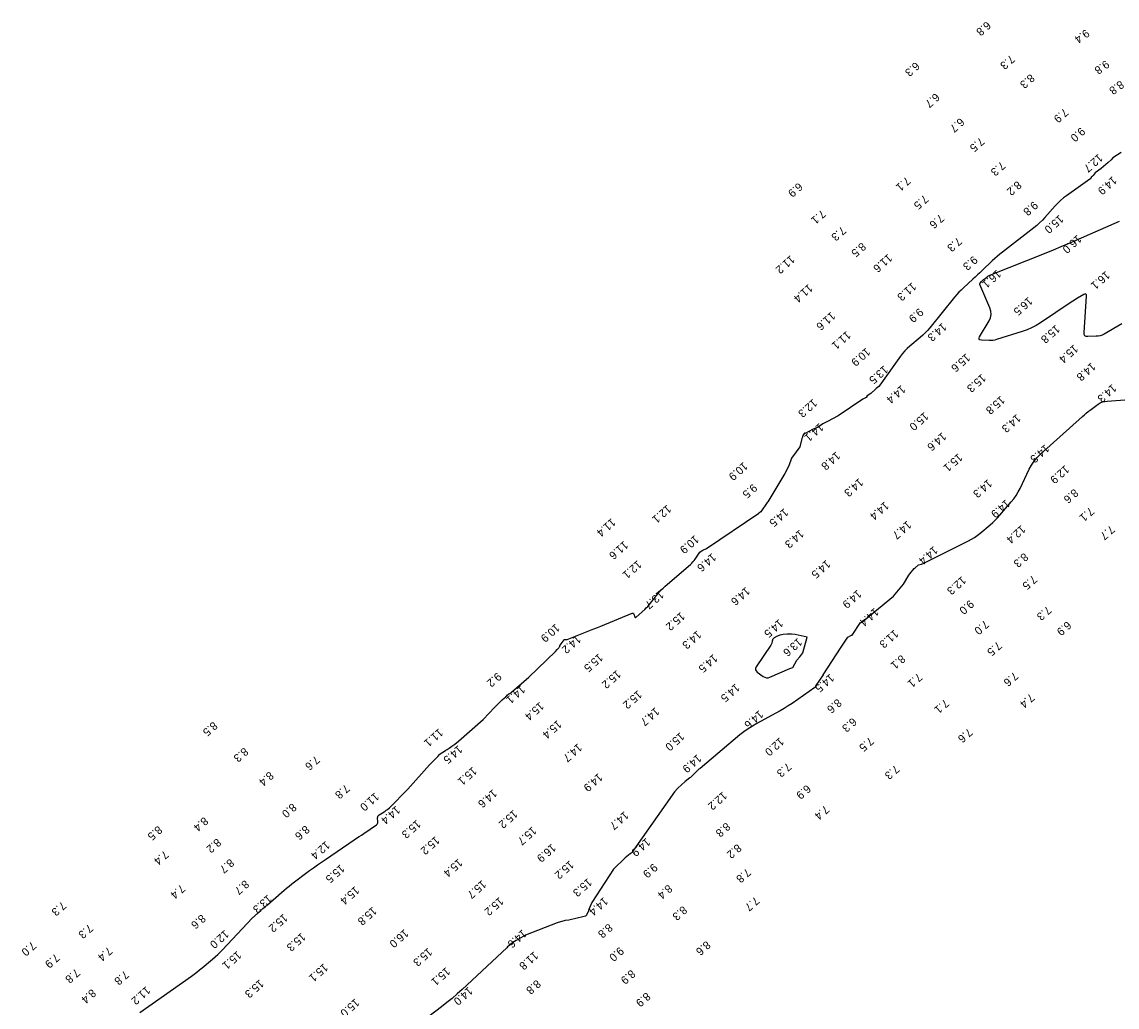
# Model space of a CAD drawing. Extents: x 824616 to 827440, y 158441 to 163197.
# Drawn here: x 825109 to 825793, y 158867 to 159482 of the extents above; entities that cross this region are included whole.
import ezdxf

# ---------------------------------------------------------------- set-up
doc = ezdxf.new("R2010")
doc.units = 0
for name, color, linetype in [('V-CHAN-CONT-EL14', 7, 'Continuous'), ('V-CHAN-CONT-EL16', 7, 'Continuous'), ('V-TOPO-SOUN', 7, 'Continuous')]:
    doc.layers.add(name, color=color, linetype=linetype)

msp = doc.modelspace()

# ---------------------------------------------------------------- linework, layer by layer
at = {"layer": 'V-CHAN-CONT-EL14'}
for points in [[(825795.5, 159400.82), (825790.27, 159397.45), (825789.29, 159396.19), (825787.45, 159394.52), (825783.02, 159390.89), (825779.27, 159388.1), (825778.07, 159386.49), (825777.36, 159385.92), (825776.81, 159385.32), (825776.65, 159385.17), (825776.33, 159384.51), (825776.22, 159384.32), (825776.17, 159384.25), (825776.11, 159384.18), (825776, 159384.1), (825761.4, 159373.83), (825759.48, 159372.4), (825757.65, 159370.87), (825755.91, 159369.23), (825754.27, 159367.49), (825747.88, 159360.31), (825746.24, 159358.56), (825744.53, 159356.89), (825742.75, 159355.29), (825740.89, 159353.78), (825721.38, 159338.58), (825719.73, 159337.26), (825718.1, 159335.9), (825716.52, 159334.5), (825714.96, 159333.06), (825708.62, 159327.04), (825707.18, 159325.68), (825705.72, 159324.32), (825704.26, 159322.97), (825702.79, 159321.63), (825696.9, 159316.28), (825695.45, 159314.92), (825694.06, 159313.51), (825692.73, 159312.04), (825691.45, 159310.52), (825675.91, 159291.28), (825674.53, 159289.67), (825673.09, 159288.13), (825671.57, 159286.66), (825669.97, 159285.27), (825663.43, 159279.84), (825661.85, 159278.44), (825660.36, 159276.95), (825658.98, 159275.36), (825657.69, 159273.68), (825644.68, 159255.52), (825644.01, 159254.6), (825643.17, 159253.95), (825642.51, 159253.38), (825641.94, 159252.92), (825639.1, 159250.38), (825636.82, 159248.76), (825636.1, 159247.88), (825634.97, 159247.23), (825634.11, 159246.64), (825618.71, 159236.3), (825611.98, 159232.84), (825609.11, 159231.24), (825606.24, 159229.33), (825602.73, 159227.8), (825598.14, 159225.26), (825598, 159225.42), (825597.86, 159225.47), (825597.71, 159225.43), (825597.56, 159225.28), (825596.74, 159224.23), (825596.7, 159224.17), (825596.69, 159224.12), (825596.67, 159224.06), (825596.64, 159223.99), (825596.56, 159223.7), (825596.51, 159223.43), (825596.38, 159222.95), (825595.96, 159222.2), (825595.98, 159222.12), (825594.66, 159216.94), (825592.44, 159213.75), (825589.57, 159209.83), (825587.88, 159205.05), (825585.33, 159200.34), (825574.67, 159182.69), (825574.31, 159182.16), (825570.45, 159176.39), (825569.05, 159175.6)], [(825659.42, 159131.15), (825662.91, 159136.91), (825663.5, 159137.59), (825666.09, 159140.9), (825666.7, 159141.46), (825668.92, 159143.18), (825670.79, 159143.76), (825671.25, 159143.92), (825671.71, 159144.09), (825672.15, 159144.28), (825672.59, 159144.49), (825700.18, 159158.32), (825702.03, 159159.32), (825703.82, 159160.42), (825705.55, 159161.62), (825707.2, 159162.92), (825713.7, 159168.34), (825715.29, 159169.72), (825716.82, 159171.17), (825718.29, 159172.68), (825719.69, 159174.26), (825726.82, 159182.59), (825728.39, 159184.56), (825729.83, 159186.62), (825731.13, 159188.77), (825732.29, 159191.01), (825738, 159202.92), (825739.44, 159205.58), (825741.11, 159208.06), (825743.02, 159210.36), (825745.17, 159212.48), (825771.37, 159235.98), (825772.53, 159237), (825773.71, 159237.99), (825774.92, 159238.95), (825776.15, 159239.88), (825781.12, 159243.56), (825782.4, 159244.37), (825783.76, 159244.98), (825785.19, 159245.38), (825786.69, 159245.58), (825800.5, 159246.43)], [(825425.49, 159073.2), (825442.07, 159089.23), (825443.14, 159090.34), (825443.91, 159091.15), (825444.2, 159091.46), (825444.41, 159091.75), (825444.63, 159092.09), (825444.74, 159092.31), (825444.83, 159092.52), (825444.89, 159092.79), (825445.05, 159093.05), (825447.5, 159096.32), (825447.62, 159096.45), (825447.76, 159096.54), (825447.91, 159096.59), (825448.08, 159096.61), (825448.81, 159096.59), (825448.99, 159096.6), (825449.17, 159096.62), (825449.35, 159096.66), (825449.52, 159096.72), (825461.91, 159101.58), (825464.04, 159102.41), (825466.15, 159103.26), (825468.27, 159104.11), (825470.38, 159104.97), (825490.06, 159113.06), (825490.43, 159113.15), (825490.73, 159113.1), (825490.96, 159112.89), (825491.12, 159112.54), (825491.61, 159110.85), (825491.76, 159110.52), (825491.95, 159110.37), (825492.2, 159110.39), (825492.5, 159110.6), (825497.85, 159115.44), (825498.83, 159116.37), (825499.77, 159117.33), (825500.66, 159118.33), (825501.52, 159119.37), (825506.02, 159125.09), (825507.08, 159126.36), (825508.19, 159127.59), (825509.36, 159128.76), (825510.59, 159129.87), (825526.39, 159143.56), (825527.21, 159144.32), (825527.97, 159145.12), (825528.67, 159145.97), (825529.31, 159146.87), (825531.79, 159150.58), (825532.37, 159151.26), (825533.07, 159151.8), (825534.2, 159152.4), (825536.47, 159153.55), (825569.05, 159175.6)], [(825609.32, 159074.51), (825620.49, 159091.91), (825621.37, 159093.08), (825624.74, 159098), (825627.12, 159099.29), (825627.41, 159099.36), (825632.65, 159107.2), (825632.85, 159107.27), (825633.05, 159107.35), (825633.24, 159107.43), (825633.44, 159107.51), (825634.22, 159107.85), (825634.38, 159107.96), (825634.49, 159108.09), (825634.54, 159108.25), (825653.23, 159123.73), (825659.42, 159131.15)], [(825599.41, 159098.15), (825591.83, 159099.81), (825589.53, 159099.87), (825587.95, 159099.87), (825586.86, 159099.99), (825584.32, 159099.81), (825582.32, 159099.33), (825579.82, 159098.29), (825579.46, 159098.14), (825578.77, 159097.58), (825578.35, 159097.32), (825578.01, 159096.95), (825577.77, 159096.53), (825577.67, 159096.16), (825577.52, 159095.54), (825577.26, 159094.26), (825576.61, 159093), (825567.54, 159079.55), (825567.09, 159078.61), (825567.04, 159077.75), (825567.38, 159076.97), (825568.13, 159076.25), (825571.94, 159073.53), (825572.9, 159073), (825573.9, 159072.75), (825574.93, 159072.78), (825575.98, 159073.11), (825588.47, 159078.58), (825590.41, 159079.15), (825592.97, 159083.76), (825594.8, 159085.88), (825596.57, 159088.34), (825599.41, 159098.15)], [(825397.01, 159046.75), (825404.02, 159054.22), (825407.2, 159057.31), (825408.86, 159059.03), (825410.26, 159060.19), (825410.8, 159060.63), (825411.21, 159060.99), (825411.44, 159061.2), (825411.55, 159061.33), (825411.62, 159061.41), (825411.68, 159061.49), (825412.18, 159062.06), (825412.28, 159062.15), (825412.37, 159062.22), (825412.48, 159062.3), (825412.6, 159062.38), (825412.77, 159062.52), (825412.96, 159062.66), (825413.13, 159062.75), (825413.52, 159063), (825414.68, 159063.83), (825425.49, 159073.2)], [(825609.32, 159074.51), (825604.81, 159067.97), (825604.77, 159067.82), (825604.54, 159067.19), (825604.48, 159067.04), (825604.39, 159066.91), (825604.28, 159066.79), (825604.15, 159066.68), (825589.9, 159056.75), (825587.45, 159055.1), (825584.97, 159053.52), (825582.43, 159052.01), (825579.85, 159050.58), (825567.95, 159044.2), (825565.15, 159042.6), (825562.43, 159040.87), (825559.81, 159038.99), (825557.29, 159036.99), (825532.4, 159016.15), (825531.73, 159015.57), (825531.07, 159014.98), (825530.43, 159014.36), (825529.8, 159013.73), (825526.92, 159010.76), (825526.48, 159010.4), (825526.01, 159010.19), (825523.16, 159007.95), (825518.58, 159003.68), (825516.51, 159001.45)], [(825349.85, 159003.06), (825363.34, 159018.26), (825368.87, 159023.83), (825369.76, 159024.77), (825370, 159025.02), (825370.16, 159025.16), (825373.35, 159027.34), (825373.73, 159027.53), (825374.06, 159027.73), (825374.53, 159028.02), (825375, 159028.34), (825375.71, 159028.82), (825376.48, 159029.36), (825377.45, 159029.91), (825379.17, 159031.26), (825381.59, 159033.04), (825397.01, 159046.75)], [(825182.54, 158863.58), (825214.67, 158886.43), (825216.39, 158887.68), (825218.08, 158888.95), (825219.76, 158890.26), (825221.41, 158891.59), (825227.98, 158896.99), (825229.6, 158898.36), (825231.17, 158899.78), (825232.69, 158901.26), (825234.17, 158902.78), (825252.73, 158922.57), (825253.04, 158922.89), (825253.36, 158923.2), (825253.69, 158923.51), (825254.03, 158923.8), (825255.4, 158924.98), (825255.73, 158925.27), (825256.06, 158925.57), (825256.38, 158925.86), (825256.7, 158926.17), (825257.98, 158927.39), (825258.3, 158927.7), (825258.63, 158927.99), (825258.96, 158928.28), (825259.3, 158928.56), (825260.74, 158929.71), (825261.09, 158930), (825261.44, 158930.29), (825261.79, 158930.58), (825262.13, 158930.88), (825270.95, 158938.63), (825272.55, 158940), (825274.17, 158941.35), (825275.82, 158942.66), (825277.49, 158943.94), (825288.57, 158952.28), (825290.99, 158954.08), (825293.43, 158955.85), (825295.89, 158957.58), (825298.38, 158959.28), (825316.41, 158971.47), (825317.9, 158972.48), (825319.39, 158973.48), (825320.87, 158974.49), (825322.36, 158975.5), (825330.27, 158980.86), (825330.71, 158981.24), (825331.01, 158981.68), (825331.18, 158982.19), (825331.2, 158982.77), (825331.04, 158985.2), (825331.07, 158985.78), (825331.24, 158986.28), (825331.55, 158986.71), (825332, 158987.07), (825335.05, 158989), (825335.73, 158989.37), (825336.36, 158989.93), (825337.17, 158990.5), (825338.44, 158991.4), (825349.85, 159003.06)], [(825516.51, 159001.45), (825490.77, 158965.07), (825490.14, 158964.06), (825489.99, 158963.65), (825488.71, 158962.78), (825485.74, 158960.29), (825478.26, 158953.1)], [(825478.26, 158953.1), (825464.77, 158932.39), (825463.39, 158929.09), (825462.92, 158927.96), (825462.73, 158927.49), (825462.65, 158927.02), (825462.48, 158926.55), (825461.35, 158924.27), (825461.07, 158923.87), (825460.79, 158923.73), (825459.19, 158923.36), (825455.57, 158922.6), (825450.42, 158921.36), (825448.17, 158921.06), (825443.14, 158919.57), (825423.46, 158911.88)], [(825423.46, 158911.88), (825417.46, 158908.63), (825415.49, 158907.29), (825413.06, 158905.35), (825412.2, 158904.63), (825411.64, 158903.96), (825383.83, 158878.04), (825380.72, 158875.21), (825377.53, 158872.46), (825374.28, 158869.8), (825370.96, 158867.21), (825355.01, 158855.13)]]:
    msp.add_lwpolyline(points, dxfattribs=at)
at = {"layer": 'V-CHAN-CONT-EL16'}
msp.add_lwpolyline([(825795.91, 159293.69), (825784.78, 159287.37), (825783.63, 159286.8), (825782.44, 159286.38), (825781.21, 159286.11), (825779.93, 159285.99), (825774.74, 159285.8), (825773.61, 159285.92), (825772.84, 159286.37), (825772.4, 159287.16), (825772.32, 159288.29), (825773.87, 159311), (825773.82, 159311.92), (825773.5, 159312.41), (825772.92, 159312.47), (825772.08, 159312.09), (825768.18, 159309.73), (825767.21, 159309.14), (825766.25, 159308.53), (825765.29, 159307.91), (825764.34, 159307.29), (825745.05, 159294.38), (825742.36, 159292.72), (825739.56, 159291.25), (825736.66, 159290), (825733.67, 159288.95), (825717.69, 159283.98), (825716.55, 159283.67), (825715.39, 159283.47), (825714.21, 159283.36), (825713.02, 159283.36), (825708.25, 159283.53), (825707.28, 159283.7), (825706.76, 159284.11), (825706.7, 159284.77), (825707.08, 159285.67), (825712.98, 159295.62), (825713.9, 159297.63), (825714.3, 159299.68), (825714.17, 159301.77), (825713.52, 159303.89), (825707.3, 159318.41), (825707.23, 159318.63), (825707.23, 159318.85), (825707.29, 159319.05), (825707.41, 159319.24), (825708.22, 159320.24), (825708.28, 159320.32), (825708.35, 159320.39), (825708.41, 159320.45), (825708.48, 159320.52), (825708.76, 159320.77), (825708.83, 159320.84), (825708.9, 159320.9), (825708.97, 159320.97), (825709.04, 159321.03), (825709.34, 159321.32), (825709.42, 159321.39), (825709.49, 159321.45), (825709.57, 159321.52), (825709.65, 159321.58), (825711.74, 159323.21), (825712.12, 159323.49), (825712.52, 159323.73), (825712.94, 159323.95), (825713.37, 159324.14), (825748.57, 159338.17), (825753.27, 159340.07), (825757.97, 159342.01), (825762.65, 159343.98), (825767.31, 159346), (825794.49, 159357.87)], dxfattribs=at)

# ---------------------------------------------------------------- texts
at = {"layer": 'V-TOPO-SOUN'}
for s, rotation, p in [('6.8', 221.4, (825711.42, 159483.09)), ('9.4', 216.2, (825773.38, 159478.07)), ('6.3', 221.4, (825666.95, 159457.68)), ('7.3', 221.4, (825726.39, 159462.04)), ('9.8', 216.2, (825785.82, 159458.73)), ('8.3', 221.4, (825738.77, 159450.18)), ('8.8', 216.2, (825794.96, 159446.04)), ('6.7', 221.4, (825679.44, 159438.23)), ('7.9', 221.4, (825759.84, 159428.77)), ('6.7', 221.4, (825694.89, 159422.75)), ('9.0', 221.4, (825770.34, 159416.88)), ('7.5', 221.4, (825707.4, 159410.62)), ('7.3', 221.4, (825720.49, 159395.54)), ('12.7 ', 221.4, (825781.36, 159400.32)), ('6.9', 221.4, (825593.86, 159382.3)), ('7.1', 221.4, (825661.27, 159385.99)), ('8.2', 221.4, (825730.57, 159383.34)), ('14.9 ', 221.4, (825790.12, 159386.24)), ('7.5', 221.4, (825672.4, 159374.64)), ('9.8', 221.4, (825740.83, 159370.73)), ('7.1', 221.4, (825608.3, 159365.37)), ('7.6', 221.4, (825682.23, 159362.67)), ('15.0 ', 221.4, (825756.86, 159362.12)), ('7.3', 221.4, (825620.94, 159354.96)), ('7.3', 221.4, (825693.29, 159348.21)), ('16.0 ', 221.4, (825768.11, 159349.64)), ('8.5', 221.4, (825633.4, 159344.91)), ('11.2 ', 221.4, (825588.97, 159336.93)), ('11.6 ', 221.4, (825649.88, 159337.77)), ('9.3', 221.4, (825703.14, 159336.58)), ('16.1 ', 221.4, (825717.87, 159327.89)), ('16.1 ', 221.4, (825785.84, 159327.06)), ('11.4 ', 221.4, (825600.22, 159318.95)), ('11.3 ', 221.4, (825664.86, 159319.95)), ('16.5 ', 221.4, (825737.54, 159310.87)), ('11.6 ', 221.4, (825614.33, 159301.6)), ('9.9', 221.4, (825669.29, 159303.98)), ('14.3 ', 221.4, (825683.85, 159294.7)), ('15.8 ', 221.4, (825754.61, 159293.44)), ('11.1 ', 221.4, (825623.99, 159289.58)), ('10.9 ', 221.4, (825636.14, 159279.16)), ('15.4 ', 221.4, (825765.95, 159281.1)), ('15.6 ', 221.4, (825698.56, 159275.54)), ('13.5 ', 221.4, (825647.29, 159268.07)), ('14.8 ', 221.4, (825776.92, 159269.93)), ('15.3 ', 221.4, (825708.39, 159262.82)), ('14.4 ', 221.4, (825658.16, 159255.8)), ('14.3 ', 221.4, (825789.97, 159256.49)), ('12.3 ', 221.4, (825602.98, 159247.19)), ('15.8 ', 221.4, (825720.23, 159249.08)), ('15.0 ', 221.4, (825672.52, 159238.95)), ('14.3 ', 221.4, (825730.17, 159237.69)), ('14.1 ', 221.4, (825606.96, 159232.02)), ('14.6 ', 221.4, (825683.63, 159226.27)), ('14.3 ', 221.4, (825747.93, 159218.78)), ('14.8 ', 221.4, (825617.41, 159214.26)), ('15.1 ', 221.4, (825693.74, 159213.17)), ('10.9 ', 221.4, (825559.59, 159207.76)), ('12.9 ', 221.4, (825760.42, 159205.79)), ('14.3 ', 221.4, (825631.76, 159197.65)), ('14.3 ', 221.4, (825712.24, 159197.01)), ('9.5', 221.4, (825565.45, 159194.22)), ('8.6', 221.4, (825766.06, 159191.09)), ('14.4 ', 221.4, (825647.78, 159183.09)), ('14.9 ', 221.4, (825723.43, 159184.4)), ('12.1 ', 221.4, (825511.8, 159181.05)), ('14.5 ', 221.4, (825584.96, 159178.86)), ('7.1', 221.4, (825775.94, 159179.61)), ('11.4 ', 221.4, (825477.12, 159172.66)), ('14.7 ', 221.4, (825661.8, 159171.1)), ('12.4 ', 221.4, (825733.1, 159168.35)), ('10.9 ', 221.4, (825529.1, 159162.06)), ('14.3 ', 221.4, (825594.67, 159165.5)), ('7.7', 221.4, (825788.77, 159168.25)), ('11.6 ', 221.4, (825484.88, 159158.47)), ('14.4 ', 221.4, (825678.32, 159155.21)), ('14.6 ', 221.4, (825539.86, 159150.85)), ('8.3', 221.4, (825734.78, 159151.05)), ('12.1 ', 221.4, (825493.31, 159146.35)), ('14.5 ', 221.4, (825611.25, 159146.62)), ('12.3 ', 221.4, (825695.97, 159136.44)), ('7.5', 221.4, (825740.28, 159137.1)), ('13.7 ', 221.4, (825507.18, 159127.53)), ('14.6 ', 221.4, (825561, 159129.74)), ('14.9 ', 221.4, (825630.68, 159127.92)), ('9.0', 221.4, (825700.88, 159121.65)), ('15.2 ', 221.4, (825520.35, 159114.04)), ('14.4 ', 221.4, (825641.42, 159116.67)), ('7.3', 221.4, (825749.24, 159117.88)), ('10.9 ', 221.4, (825442.17, 159106.77)), ('14.5 ', 221.4, (825581.72, 159109.64)), ('7.0', 221.4, (825710.26, 159109.02)), ('6.9', 221.4, (825761.7, 159108.39)), ('14.2 ', 221.4, (825455.4, 159099.68)), ('14.3 ', 221.4, (825530.63, 159102.52)), ('11.3 ', 221.4, (825653.75, 159103.08)), ('13.6 ', 221.4, (825593.59, 159097.9)), ('7.5', 221.4, (825718.22, 159095.7)), ('15.5 ', 221.4, (825469.18, 159088.17)), ('14.5 ', 221.4, (825540.76, 159087.79)), ('8.1', 221.4, (825658.03, 159087.38)), ('9.2', 221.4, (825405.74, 159076.33)), ('15.2 ', 221.4, (825480.36, 159077.82)), ('14.5 ', 221.4, (825613.6, 159075.5)), ('7.1', 221.4, (825668.56, 159075.96)), ('7.6', 221.4, (825728.54, 159076.75)), ('14.1 ', 221.4, (825420.57, 159068.27)), ('14.5 ', 221.4, (825554.59, 159069.4)), ('15.2 ', 221.4, (825493.54, 159065.14)), ('8.6', 221.4, (825618.21, 159059.95)), ('7.1', 221.4, (825685.29, 159059.69)), ('7.4', 221.4, (825738.68, 159063.21)), ('15.4 ', 221.4, (825432.3, 159057.9)), ('14.7 ', 221.4, (825504.4, 159054.54)), ('14.6 ', 221.4, (825569.34, 159052.73)), ('8.5', 221.4, (825228.31, 159045.65)), ('15.4 ', 221.4, (825443.36, 159046.55)), ('6.3', 221.4, (825627.63, 159048.14)), ('11.1 ', 221.4, (825369.32, 159041.38)), ('15.0 ', 221.4, (825520, 159038.89)), ('7.6', 221.4, (825699.97, 159041.54)), ('14.7 ', 221.4, (825456.11, 159032)), ('12.0 ', 221.4, (825582.22, 159035.75)), ('7.5', 221.4, (825638.27, 159036.04)), ('8.3', 221.4, (825247.57, 159029.46)), ('14.5 ', 221.4, (825381.37, 159030.88)), ('14.9 ', 221.4, (825530.73, 159025.22)), ('7.6', 221.4, (825292.2, 159024.37)), ('15.1 ', 221.4, (825390.37, 159017.36)), ('7.3', 221.4, (825586.83, 159020.04)), ('7.3', 221.4, (825654.29, 159018.57)), ('8.4', 221.4, (825263.4, 159014.49)), ('14.9 ', 221.4, (825468.95, 159013.41)), ('7.8', 221.4, (825310.9, 159006.49)), ('6.9', 221.4, (825599, 159006.27)), ('11.0 ', 221.4, (825329.32, 159001.34)), ('14.6 ', 221.4, (825402.99, 159003.39)), ('12.2 ', 221.4, (825546.68, 159001.97)), ('8.0', 221.4, (825277.69, 158994.68)), ('14.4 ', 221.4, (825342.49, 158993.04)), ('15.2 ', 221.4, (825415.9, 158990.5)), ('7.4', 221.4, (825610.46, 158993.35)), ('8.4', 221.4, (825222.54, 158986.11)), ('15.3 ', 221.4, (825355.37, 158984.26)), ('14.7 ', 221.4, (825485.2, 158989.64)), ('8.5', 221.4, (825193.82, 158980.6)), ('8.6', 221.4, (825285.87, 158980.83)), ('15.7 ', 221.4, (825427.67, 158980.06)), ('8.8', 221.4, (825548.7, 158982.64)), ('8.2', 221.4, (825230.61, 158972.72)), ('12.4 ', 221.4, (825298.62, 158971.04)), ('15.2 ', 221.4, (825367.15, 158974.05)), ('14.9 ', 221.4, (825498.76, 158972.94)), ('7.4', 221.4, (825197.79, 158965.19)), ('16.9 ', 221.4, (825439.75, 158969.34)), ('8.2', 221.4, (825555.64, 158969.24)), ('8.7', 221.4, (825238.74, 158960.02)), ('15.5 ', 221.4, (825307.8, 158956.41)), ('15.4 ', 221.4, (825381.47, 158960.04)), ('15.2 ', 221.4, (825450.97, 158958.86)), ('9.9', 221.4, (825503.23, 158957.07)), ('7.8', 221.4, (825561.48, 158954.05)), ('7.4', 221.4, (825208.14, 158943.97)), ('8.7', 221.4, (825248.06, 158946.68)), ('15.4 ', 221.4, (825316.95, 158942.84)), ('15.7 ', 221.4, (825396.22, 158946.62)), ('15.3 ', 221.4, (825462.29, 158947.83)), ('8.4', 221.4, (825512.44, 158943.89)), ('13.3 ', 221.4, (825262.4, 158937.52)), ('15.2 ', 221.4, (825407.06, 158936.02)), ('14.4 ', 221.4, (825472.33, 158936)), ('7.7', 221.4, (825566.83, 158936.37)), ('7.3', 221.4, (825133.85, 158933.35)), ('15.8 ', 221.4, (825327.88, 158929.97)), ('8.3', 221.4, (825521.69, 158930.53)), ('8.6', 221.4, (825220.97, 158925.26)), ('15.2 ', 221.4, (825272.24, 158925.62)), ('7.3', 221.4, (825150.6, 158919.21)), ('12.0 ', 221.4, (825235.52, 158915.49)), ('16.0 ', 221.4, (825347.71, 158915.96)), ('14.6 ', 221.4, (825421.48, 158915.81)), ('8.8', 221.4, (825475.15, 158919.52)), ('15.3 ', 221.4, (825283.49, 158913.74)), ('8.6', 221.4, (825536.34, 158908.68)), ('7.0', 221.4, (825115.03, 158908.31)), ('7.4', 221.4, (825162.69, 158905.04)), ('15.1 ', 221.4, (825243.29, 158902.39)), ('15.3 ', 221.4, (825362.51, 158904.34)), ('11.8 ', 221.4, (825428.74, 158902.1)), ('9.0', 221.4, (825482.18, 158904.95)), ('7.9', 221.4, (825129.71, 158900.76)), ('15.1 ', 221.4, (825297.38, 158894.59)), ('7.8', 221.4, (825142.4, 158891.34)), ('7.8', 221.4, (825173.02, 158890.17)), ('15.1 ', 221.4, (825373.74, 158892.2)), ('8.9', 221.4, (825489.36, 158890.69)), ('15.3 ', 221.4, (825257.33, 158884.59)), ('8.8', 221.4, (825430.31, 158884.4)), ('8.4', 221.4, (825152.44, 158878.66)), ('11.2 ', 221.4, (825186.45, 158880.35)), ('14.0 ', 221.4, (825387.78, 158880.01)), ('8.9', 221.4, (825498.81, 158876.54)), ('15.0 ', 221.4, (825317, 158872.68))]:
    msp.add_text(s, height=5, rotation=rotation, dxfattribs=at).set_placement(p)

doc.saveas('drawing.dxf')
